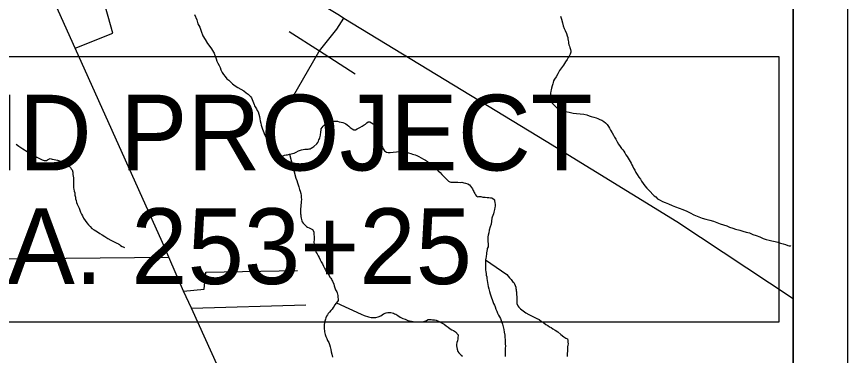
# Model space of a CAD drawing. Extents: x 0 to 44.3, y 0 to 22.
# Drawn here: x 7.465 to 9, y 16.414 to 17.041 of the extents above; entities that cross this region are included whole.
import ezdxf

# ---------------------------------------------------------------- set-up
doc = ezdxf.new("R2010")
doc.units = 0
for name, color, linetype in [('GM_X_City_Street', 7, 'Continuous'), ('GM_X_Corporation', 7, 'Continuous'), ('GM_X_County_Road', 7, 'Continuous'), ('GM_X_Minor_River', 7, 'Continuous'), ('GM_X_State_Route', 7, 'Continuous'), ('SH_Data', 7, 'Continuous'), ('SH_Text', 7, 'Continuous')]:
    doc.layers.add(name, color=color, linetype=linetype)

msp = doc.modelspace()

# ---------------------------------------------------------------- linework, layer by layer
at = {"layer": 'GM_X_City_Street'}
for p, q in [((7.6428, 17.0099), (7.6112, 17.1221)), ((7.573, 16.9823), (7.6428, 17.0099)), ((7.405, 16.5925), (7.7462, 16.5959)), ((7.7879, 16.5017), (7.9995, 16.5079))]:
    msp.add_line(p, q, dxfattribs=at)
for points in [[(7.9747, 16.8914), (8.023, 16.9757), (8.0243, 16.9774), (8.0563, 17.0177), (8.0693, 17.038)], [(7.9686, 17.0133), (8.0243, 16.9774), (8.0903, 16.9349)], [(7.7731, 16.5331), (7.8116, 16.5367), (7.8142, 16.5684), (7.984, 16.5714)]]:
    msp.add_lwpolyline(points, dxfattribs=at)
at = {"layer": 'GM_X_Corporation'}
for points in [[(8.9, 14.1), (8.9, 20.9), (3.6041, 20.9)], [(8.9, 14.1), (8.9, 20.9), (3.6041, 20.9)], [(8.9, 14.1), (8.9, 17.4522)]]:
    msp.add_lwpolyline(points, dxfattribs=at)
at = {"layer": 'GM_X_County_Road'}
msp.add_lwpolyline([(7.8287, 17.19), (7.8303, 17.1888), (7.8776, 17.1561), (7.9052, 17.138), (8.0617, 17.0432), (8.0693, 17.038), (8.4435, 16.8101), (8.6847, 16.6618), (8.9, 16.5192)], dxfattribs=at)
at = {"layer": 'GM_X_Minor_River'}
for points in [[(7.7937, 17.0445), (7.798, 17.0347), (7.8, 17.0275), (7.8032, 17.0211), (7.8056, 17.0135), (7.8087, 17.0052), (7.813, 16.9984), (7.8173, 16.9912), (7.8216, 16.9856), (7.8247, 16.9811), (7.8271, 16.9777), (7.8286, 16.9751), (7.8298, 16.9728), (7.8306, 16.9709), (7.8314, 16.9683), (7.8326, 16.966), (7.8338, 16.9626), (7.835, 16.9584), (7.8369, 16.9543), (7.8389, 16.9505), (7.8409, 16.9463), (7.8425, 16.9422), (7.8448, 16.9376), (7.8472, 16.9335), (7.8503, 16.9297), (7.853, 16.9256), (7.8568, 16.923), (7.8595, 16.9204), (7.8638, 16.9163), (7.8684, 16.9129), (7.8738, 16.9096), (7.8791, 16.9066), (7.8845, 16.9036), (7.8891, 16.8999), (7.893, 16.8973)], [(8.4697, 17.0412), (8.472, 17.0359), (8.4737, 17.0291), (8.4749, 17.0238), (8.4769, 17.0189), (8.4785, 17.0147), (8.4808, 17.0094), (8.4824, 17.0052), (8.4832, 17.0022), (8.4837, 16.9996), (8.4841, 16.9965), (8.4845, 16.9939), (8.4849, 16.9916), (8.4854, 16.9882), (8.4865, 16.9859), (8.4873, 16.9836), (8.4878, 16.9817), (8.4885, 16.9799), (8.489, 16.9768), (8.489, 16.9749), (8.4875, 16.9711), (8.4857, 16.9676), (8.4842, 16.965), (8.482, 16.9611), (8.479, 16.9569), (8.4753, 16.9511), (8.4716, 16.9461), (8.4679, 16.9408), (8.465, 16.9346), (8.4616, 16.9293), (8.459, 16.9247), (8.4572, 16.9216), (8.4561, 16.9189), (8.4554, 16.9162), (8.4547, 16.9124), (8.4532, 16.9086), (8.4525, 16.9052), (8.4518, 16.9025), (8.4515, 16.8991), (8.4512, 16.8964), (8.4508, 16.8937), (8.4509, 16.8907), (8.4517, 16.8869), (8.4529, 16.8835), (8.4548, 16.8801), (8.4579, 16.8767), (8.4633, 16.8719), (8.4794, 16.8653), (8.4859, 16.8638), (8.4931, 16.8624), (8.4996, 16.8614), (8.5065, 16.8607), (8.5129, 16.8601), (8.5183, 16.859), (8.5228, 16.8575), (8.5267, 16.8561), (8.5316, 16.8546), (8.5355, 16.8532), (8.5389, 16.8521), (8.5427, 16.8506), (8.5465, 16.8491), (8.55, 16.8469), (8.5531, 16.8443), (8.5558, 16.8409), (8.5585, 16.8375), (8.5605, 16.8341), (8.5624, 16.8307), (8.5652, 16.8258), (8.5675, 16.8217), (8.5699, 16.8179), (8.5722, 16.8138), (8.5746, 16.8092), (8.5773, 16.8047), (8.58, 16.8006), (8.5827, 16.7968), (8.5851, 16.7942), (8.587, 16.7916), (8.5886, 16.7889), (8.5905, 16.7852), (8.5929, 16.7821), (8.5948, 16.7787), (8.5968, 16.7757), (8.5987, 16.7727), (8.6003, 16.7697), (8.6019, 16.7667), (8.6034, 16.7637), (8.605, 16.7603), (8.607, 16.7565), (8.6089, 16.7527), (8.6116, 16.7486), (8.6148, 16.7441), (8.6175, 16.7403)], [(7.893, 16.8973), (7.8953, 16.895), (7.8972, 16.8932), (7.8988, 16.8902), (7.9004, 16.8875), (7.9015, 16.8845), (7.9024, 16.8811), (7.9035, 16.8781), (7.9047, 16.8758), (7.9059, 16.8739), (7.9067, 16.872), (7.9079, 16.8701), (7.9094, 16.8671), (7.9114, 16.8645), (7.9138, 16.8558), (7.9142, 16.8516), (7.9151, 16.8478), (7.9159, 16.8436), (7.9167, 16.8398), (7.9179, 16.8361), (7.9191, 16.8323), (7.9215, 16.8266), (7.9231, 16.8228), (7.925, 16.8187), (7.927, 16.8141), (7.929, 16.81), (7.9313, 16.8058), (7.9337, 16.8013), (7.936, 16.7975), (7.938, 16.7941), (7.9399, 16.7911), (7.9419, 16.7889), (7.9438, 16.7874), (7.9457, 16.7863), (7.9484, 16.7848), (7.9515, 16.7829), (7.9534, 16.7822), (7.9572, 16.783), (7.9598, 16.7842), (7.9628, 16.785), (7.9655, 16.7854), (7.9689, 16.7862), (7.9723, 16.7867), (7.9749, 16.7875), (7.978, 16.7883), (7.9814, 16.7898), (7.9859, 16.7922), (7.9915, 16.7946), (7.9972, 16.7954), (8.0007, 16.7955), (8.0033, 16.7955), (8.0052, 16.7959), (8.0075, 16.7963), (8.0094, 16.7975), (8.012, 16.799), (8.0143, 16.8002), (8.0195, 16.8056), (8.0213, 16.8079), (8.0224, 16.8102), (8.0232, 16.8129), (8.0243, 16.8148), (8.025, 16.8167), (8.0257, 16.819), (8.0261, 16.8213), (8.0264, 16.8232), (8.0268, 16.8255), (8.0271, 16.8278), (8.0274, 16.8305), (8.0278, 16.8331), (8.0293, 16.8358), (8.0311, 16.8381), (8.0334, 16.84), (8.0356, 16.8416), (8.0375, 16.8424), (8.0401, 16.8439), (8.0435, 16.8451), (8.0462, 16.8456), (8.0481, 16.8463), (8.0511, 16.8472), (8.0534, 16.8476), (8.0553, 16.8476), (8.0579, 16.8473), (8.061, 16.8462), (8.0648, 16.8455), (8.0679, 16.8447), (8.0705, 16.8436), (8.0732, 16.8422), (8.0759, 16.8407), (8.0786, 16.8384), (8.0809, 16.8358), (8.0848, 16.8332), (8.0882, 16.8313), (8.0909, 16.8314), (8.0943, 16.8333), (8.0992, 16.8357), (8.1033, 16.8384), (8.1071, 16.8408), (8.1093, 16.8419), (8.1119, 16.8442), (8.1146, 16.8462), (8.1176, 16.8462)], [(8.1176, 16.8462), (8.1238, 16.8425), (8.1257, 16.8406), (8.1276, 16.8388), (8.1288, 16.8369), (8.13, 16.8346), (8.1312, 16.8312), (8.132, 16.8263), (8.1336, 16.8221), (8.1344, 16.8183), (8.1352, 16.8153), (8.136, 16.8127), (8.1372, 16.8096), (8.138, 16.8062), (8.1392, 16.8032), (8.14, 16.8013), (8.1412, 16.7994), (8.142, 16.7964), (8.1432, 16.7941), (8.1447, 16.7923), (8.1485, 16.79), (8.1516, 16.7893), (8.1554, 16.7894), (8.1607, 16.7898), (8.1668, 16.7907), (8.1725, 16.7915), (8.1782, 16.7916), (8.1827, 16.7909), (8.1862, 16.7902), (8.1892, 16.7887), (8.1934, 16.7877), (8.1961, 16.7866), (8.1988, 16.7858), (8.2014, 16.7851), (8.2045, 16.7836), (8.2083, 16.7818), (8.2122, 16.7796), (8.2164, 16.7773), (8.2202, 16.7751), (8.2241, 16.7725), (8.2272, 16.7699), (8.2314, 16.7662), (8.2345, 16.7635), (8.2376, 16.7613), (8.2406, 16.7583), (8.2441, 16.7553), (8.2472, 16.7523), (8.2503, 16.7489), (8.253, 16.7463), (8.2557, 16.7437), (8.2627, 16.7362), (8.2653, 16.7351), (8.2672, 16.7347), (8.2695, 16.7344), (8.2726, 16.7344), (8.276, 16.7345), (8.2802, 16.7346), (8.2844, 16.7342), (8.2878, 16.7343), (8.2912, 16.7336), (8.2946, 16.7325), (8.2985, 16.7314), (8.3019, 16.7296), (8.3038, 16.7273), (8.3054, 16.725), (8.3073, 16.7224), (8.3085, 16.7194), (8.3097, 16.7175), (8.3105, 16.7156), (8.3113, 16.7137), (8.3129, 16.7111), (8.3148, 16.7084), (8.3171, 16.7077), (8.319, 16.7078), (8.3224, 16.7078), (8.3266, 16.7071), (8.3304, 16.7068), (8.3342, 16.7065), (8.3376, 16.7061), (8.3403, 16.7058), (8.3426, 16.7054), (8.3445, 16.7047), (8.3476, 16.7021), (8.348, 16.6998), (8.3488, 16.6968), (8.3489, 16.6934), (8.3489, 16.6899), (8.3486, 16.6877), (8.3482, 16.6842), (8.3475, 16.6816), (8.3468, 16.6793), (8.3461, 16.6762), (8.345, 16.6732), (8.3439, 16.6701), (8.3432, 16.6682), (8.3415, 16.6571), (8.3397, 16.6518), (8.3382, 16.6461), (8.3372, 16.6411), (8.3361, 16.6365), (8.3354, 16.6335)], [(7.464, 16.805), (7.469, 16.8009), (7.4763, 16.7961), (7.4844, 16.7912), (7.4909, 16.7872), (7.4962, 16.7842), (7.5001, 16.782), (7.5024, 16.7805), (7.5047, 16.7794), (7.507, 16.7786), (7.5093, 16.7772), (7.5123, 16.7757), (7.5158, 16.7746), (7.5177, 16.7746), (7.5203, 16.7747), (7.5222, 16.7758), (7.5241, 16.777), (7.5271, 16.7782), (7.5306, 16.7771), (7.5344, 16.7764), (7.5374, 16.7761), (7.5405, 16.7753), (7.5443, 16.7743), (7.5481, 16.7728), (7.5516, 16.7713), (7.5546, 16.7706), (7.5577, 16.7691), (7.5596, 16.7673), (7.5643, 16.7616), (7.5658, 16.7594), (7.5674, 16.7571), (7.5689, 16.7533), (7.569, 16.7488), (7.5699, 16.7423), (7.57, 16.7359), (7.5701, 16.7309), (7.5701, 16.7275), (7.5702, 16.7244), (7.5706, 16.7214), (7.5714, 16.718), (7.5722, 16.7146), (7.5727, 16.7104), (7.5735, 16.707), (7.5739, 16.7036), (7.5748, 16.7006), (7.5756, 16.6971), (7.5768, 16.6941), (7.5787, 16.69), (7.5803, 16.6866), (7.5815, 16.6828), (7.5831, 16.6794), (7.5847, 16.6756), (7.5866, 16.6722), (7.5886, 16.6681), (7.5913, 16.6639), (7.5944, 16.6594), (7.5975, 16.6556), (7.601, 16.6527), (7.6041, 16.6489), (7.6083, 16.6467), (7.6114, 16.6444), (7.6145, 16.6426), (7.6183, 16.6396), (7.6229, 16.637), (7.6279, 16.634), (7.6333, 16.6307), (7.6387, 16.6274), (7.644, 16.6251), (7.6475, 16.6233), (7.6501, 16.6218), (7.6528, 16.6207), (7.6547, 16.6192), (7.657, 16.6177), (7.6597, 16.6159), (7.662, 16.6148), (7.6639, 16.614)], [(7.9689, 16.7862), (7.981, 16.7419), (7.9826, 16.7378), (7.9838, 16.7336), (7.9854, 16.7298), (7.9866, 16.726), (7.9878, 16.7211), (7.989, 16.7177), (7.9898, 16.7139), (7.9907, 16.7101), (7.9907, 16.7063), (7.9912, 16.7025), (7.9908, 16.6991), (7.9905, 16.6957), (7.9902, 16.6926), (7.9899, 16.6892), (7.9895, 16.6858), (7.9892, 16.6831), (7.9897, 16.6759), (7.9901, 16.674), (7.9902, 16.671), (7.9906, 16.6683), (7.991, 16.6656), (7.9918, 16.663), (7.9926, 16.6611), (7.9942, 16.6585), (7.9969, 16.6562), (8.0003, 16.6528), (8.0026, 16.6514), (8.0053, 16.6499), (8.008, 16.6488), (8.0114, 16.6473), (8.0138, 16.6428), (8.0144, 16.6295), (8.0141, 16.623), (8.0145, 16.6204), (8.015, 16.6181), (8.0154, 16.615), (8.0158, 16.6128), (8.0162, 16.6109), (8.0166, 16.609), (8.0178, 16.6067), (8.0186, 16.6044), (8.0202, 16.6018), (8.0218, 16.5984), (8.0237, 16.595), (8.0257, 16.5912), (8.0276, 16.5875), (8.03, 16.5833), (8.0319, 16.5795), (8.0335, 16.5758), (8.0355, 16.5724), (8.037, 16.5697), (8.0386, 16.5675), (8.0405, 16.5648), (8.0421, 16.5622), (8.0437, 16.5592), (8.0452, 16.5569), (8.0464, 16.555), (8.0472, 16.5532), (8.0484, 16.5513), (8.0511, 16.546), (8.0519, 16.543), (8.0527, 16.5395), (8.0543, 16.5358), (8.0551, 16.5339), (8.0563, 16.5316), (8.0571, 16.5297), (8.0579, 16.5275), (8.0583, 16.5248), (8.0587, 16.5218), (8.0588, 16.5183), (8.0588, 16.5161), (8.0562, 16.5115), (8.0525, 16.5072), (8.0514, 16.5053), (8.0495, 16.5026), (8.0477, 16.4999), (8.0454, 16.4972), (8.0428, 16.4941), (8.0406, 16.4915), (8.0391, 16.4892), (8.0376, 16.4868), (8.0365, 16.4838), (8.0354, 16.4815), (8.0347, 16.4796), (8.0344, 16.4777), (8.034, 16.475), (8.0333, 16.4708), (8.0331, 16.4651), (8.0336, 16.4579), (8.0348, 16.453), (8.0364, 16.4492), (8.0379, 16.4454), (8.0395, 16.4416), (8.0415, 16.4382), (8.0431, 16.4344)], [(8.6175, 16.7403), (8.6198, 16.7365), (8.6226, 16.7324), (8.6257, 16.7279), (8.6295, 16.7237), (8.6334, 16.7196), (8.6431, 16.7095), (8.6461, 16.7073), (8.6492, 16.7039), (8.6542, 16.7013), (8.6584, 16.6991), (8.6634, 16.6969), (8.6695, 16.6943), (8.676, 16.6917), (8.6822, 16.6892), (8.689, 16.6866), (8.6959, 16.684), (8.7032, 16.6807), (8.7097, 16.6778), (8.7162, 16.6744), (8.7254, 16.6704), (8.7319, 16.6682), (8.7384, 16.666), (8.7456, 16.6646), (8.7525, 16.6624), (8.759, 16.6599), (8.7651, 16.6577), (8.7712, 16.6559), (8.777, 16.6537), (8.7823, 16.6515), (8.7881, 16.6496), (8.7934, 16.6474), (8.801, 16.646), (8.8071, 16.6442), (8.8129, 16.6424), (8.819, 16.6406), (8.8251, 16.638), (8.8316, 16.6358), (8.8381, 16.6333), (8.8442, 16.6307), (8.85, 16.6285), (8.8553, 16.6274), (8.8603, 16.626), (8.8667, 16.6246), (8.8717, 16.6235), (8.8767, 16.6221), (8.8812, 16.6206), (8.8854, 16.6191), (8.8897, 16.6177), (8.8927, 16.617), (8.8946, 16.6166), (8.8954, 16.6162)], [(8.3354, 16.6335), (8.3354, 16.6308), (8.3355, 16.6285), (8.3355, 16.6259), (8.3356, 16.624), (8.336, 16.6213), (8.3364, 16.619), (8.3364, 16.6171), (8.3361, 16.6148), (8.3346, 16.6118), (8.3343, 16.6099), (8.3339, 16.6068), (8.3332, 16.6038), (8.3329, 16.6011), (8.3326, 16.5984), (8.3322, 16.5965), (8.3319, 16.5939), (8.3312, 16.5908), (8.3312, 16.5874), (8.3313, 16.584), (8.331, 16.5805), (8.331, 16.5764), (8.3315, 16.5726), (8.3319, 16.5691), (8.3323, 16.5657), (8.3328, 16.5627), (8.3336, 16.5593), (8.334, 16.5562), (8.3365, 16.5418), (8.3377, 16.5373), (8.3386, 16.5324), (8.3398, 16.5282), (8.341, 16.5244), (8.3426, 16.5206), (8.3438, 16.5176), (8.345, 16.5138), (8.3462, 16.5104), (8.3477, 16.507), (8.3489, 16.504), (8.3501, 16.4998), (8.3521, 16.4961), (8.3537, 16.4923), (8.3553, 16.4889), (8.3572, 16.4855), (8.3588, 16.4825), (8.3604, 16.4791), (8.3616, 16.4757), (8.3628, 16.4719), (8.364, 16.4673), (8.3652, 16.4624), (8.366, 16.4575), (8.3669, 16.4518), (8.3673, 16.4476), (8.3678, 16.4434), (8.3678, 16.4392), (8.3679, 16.4358), (8.368, 16.4316), (8.3677, 16.4278), (8.3677, 16.424), (8.3674, 16.4198), (8.3675, 16.416), (8.3675, 16.4122)], [(8.3312, 16.5908), (8.3704, 16.5636), (8.3731, 16.5606), (8.3758, 16.5576), (8.3785, 16.5546), (8.3812, 16.5512), (8.3835, 16.549), (8.3851, 16.5467), (8.3859, 16.5437), (8.3871, 16.5407), (8.3875, 16.538), (8.3879, 16.5361), (8.388, 16.5338), (8.3884, 16.5316), (8.3884, 16.5289), (8.3889, 16.5206), (8.3891, 16.5133), (8.3891, 16.5103), (8.3911, 16.5061), (8.393, 16.5035), (8.3961, 16.5005), (8.4007, 16.4964), (8.4061, 16.493), (8.4115, 16.4901), (8.4165, 16.4875), (8.4214, 16.4849), (8.4264, 16.4827), (8.4306, 16.4805), (8.4345, 16.4771), (8.4391, 16.4745), (8.4429, 16.4715), (8.4464, 16.4693), (8.4495, 16.4671), (8.4525, 16.4656), (8.456, 16.4637), (8.4602, 16.4611), (8.4648, 16.4578), (8.4706, 16.4529), (8.476, 16.4488), (8.4798, 16.4462), (8.4829, 16.4447), (8.4837, 16.4417), (8.4837, 16.4387), (8.4838, 16.436), (8.4835, 16.433), (8.4831, 16.4299), (8.4828, 16.4261), (8.4825, 16.4219), (8.4822, 16.4177), (8.4823, 16.4124)], [(8.0562, 16.5115), (8.1018, 16.4905), (8.1072, 16.4879), (8.1148, 16.4857), (8.1201, 16.4846), (8.1247, 16.4843), (8.1285, 16.4844), (8.1327, 16.4856), (8.1376, 16.4876), (8.1428, 16.4911), (8.1477, 16.4927), (8.1511, 16.4935), (8.1538, 16.4939), (8.1561, 16.4935), (8.1588, 16.4928), (8.161, 16.4921), (8.163, 16.4914), (8.1656, 16.4903), (8.1691, 16.488), (8.1733, 16.485), (8.1783, 16.4828), (8.1829, 16.481), (8.1879, 16.4788), (8.1943, 16.4774), (8.2016, 16.4763), (8.2084, 16.4761), (8.2153, 16.4765), (8.2194, 16.4777), (8.2221, 16.4789), (8.2251, 16.4805), (8.2281, 16.4805), (8.2308, 16.4806), (8.2334, 16.4802), (8.2369, 16.4799), (8.2403, 16.4792), (8.2456, 16.477), (8.2502, 16.4748), (8.2548, 16.4722), (8.2587, 16.4692), (8.2625, 16.4666), (8.266, 16.4636), (8.2691, 16.4617), (8.2721, 16.4603), (8.2741, 16.4592), (8.276, 16.458), (8.2806, 16.4524), (8.2807, 16.4505), (8.2803, 16.4482), (8.28, 16.4452), (8.2793, 16.4414), (8.2782, 16.4379), (8.2779, 16.4345), (8.2779, 16.4318), (8.278, 16.4288), (8.2788, 16.4258), (8.2804, 16.4216), (8.2823, 16.4193), (8.2842, 16.4167), (8.2866, 16.4149), (8.2885, 16.413)], [(8.0431, 16.4344), (8.0443, 16.4303), (8.0455, 16.4254), (8.0463, 16.4208), (8.0475, 16.4166), (8.0484, 16.411)]]:
    msp.add_lwpolyline(points, dxfattribs=at)
at = {"layer": 'GM_X_State_Route'}
for points in [[(7.7342, 16.6228), (7.573, 16.9823), (7.4947, 17.1569), (7.4762, 17.1977), (7.4726, 17.2055)], [(7.8494, 16.3654), (7.7879, 16.5017), (7.7731, 16.5331), (7.7462, 16.5959), (7.7342, 16.6228)]]:
    msp.add_lwpolyline(points, dxfattribs=at)
at = {"layer": 'SH_Data'}
for p, q in [((9, 21), (9, 14)), ((8.9, 20.9), (8.9, 14.1)), ((8.9, 20.9), (8.9, 14.1))]:
    msp.add_line(p, q, dxfattribs=at)
at = {"layer": 'SH_Text'}
msp.add_lwpolyline([(7.1384, 16.4762), (8.8739, 16.4762), (8.8739, 16.9662), (7.1384, 16.9662)], close=True, dxfattribs=at)

# ---------------------------------------------------------------- texts
for s, p in [('END PROJECT', (7.2084, 16.7562)), ('STA. 253+25', (7.2084, 16.5462))]:
    msp.add_text(s, height=0.14, dxfattribs=at).set_placement(p)

doc.saveas('drawing.dxf')
